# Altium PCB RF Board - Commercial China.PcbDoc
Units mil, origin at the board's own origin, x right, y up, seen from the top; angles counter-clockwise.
Board outline 2000 x 1000 mil, 2 copper layers (Top Layer, Bottom Layer); 17 components, 17 nets, 58 pads, 9 vias.
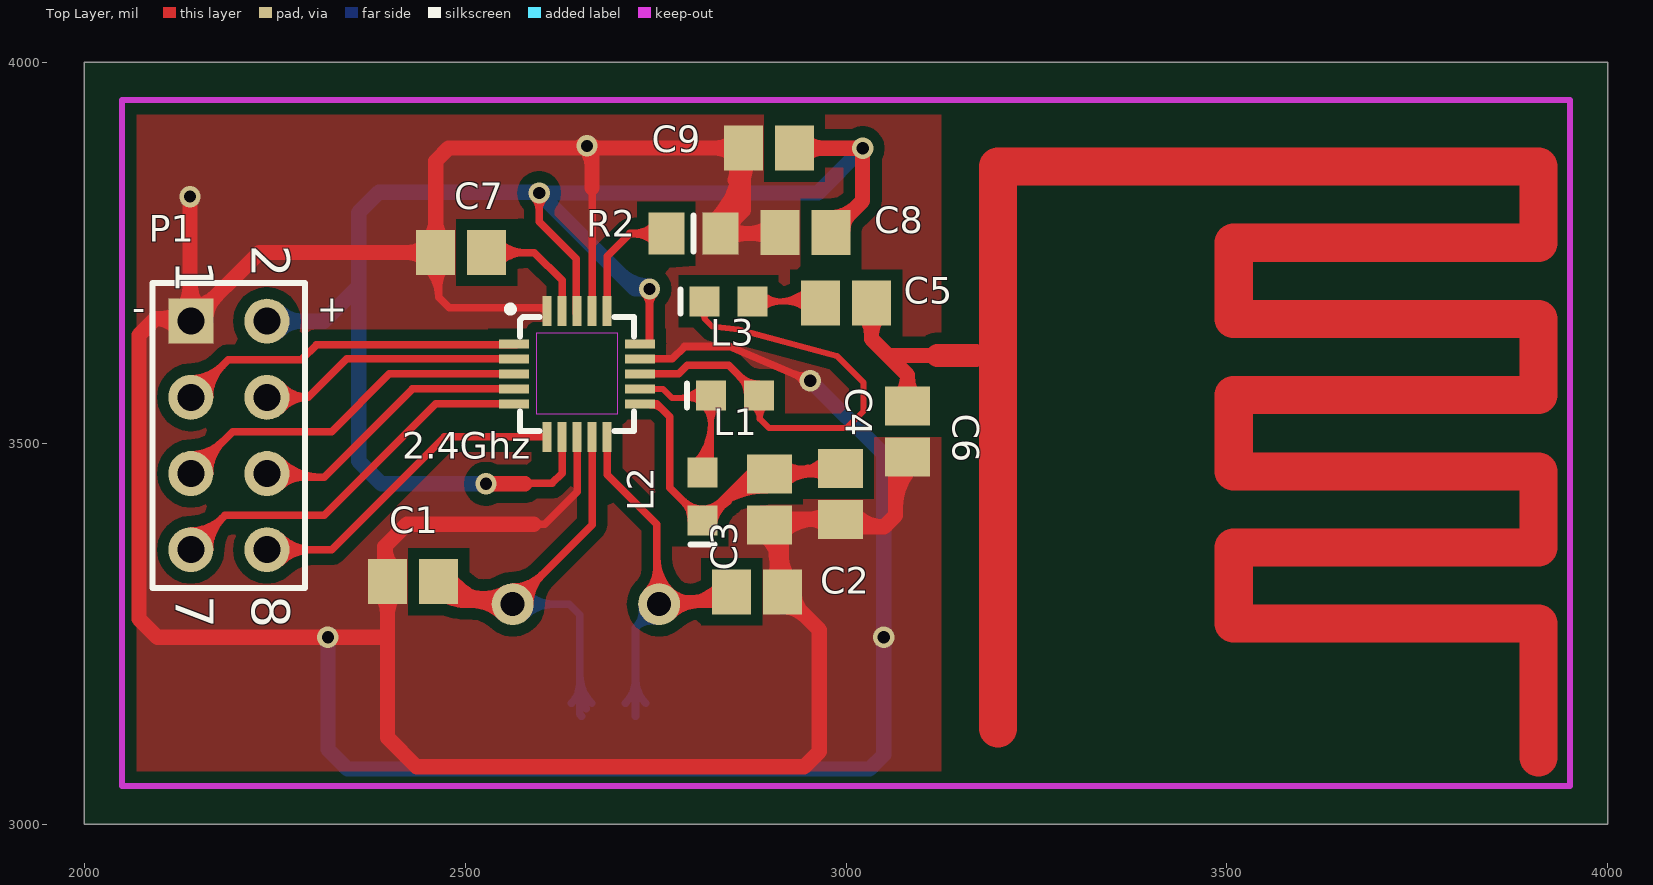
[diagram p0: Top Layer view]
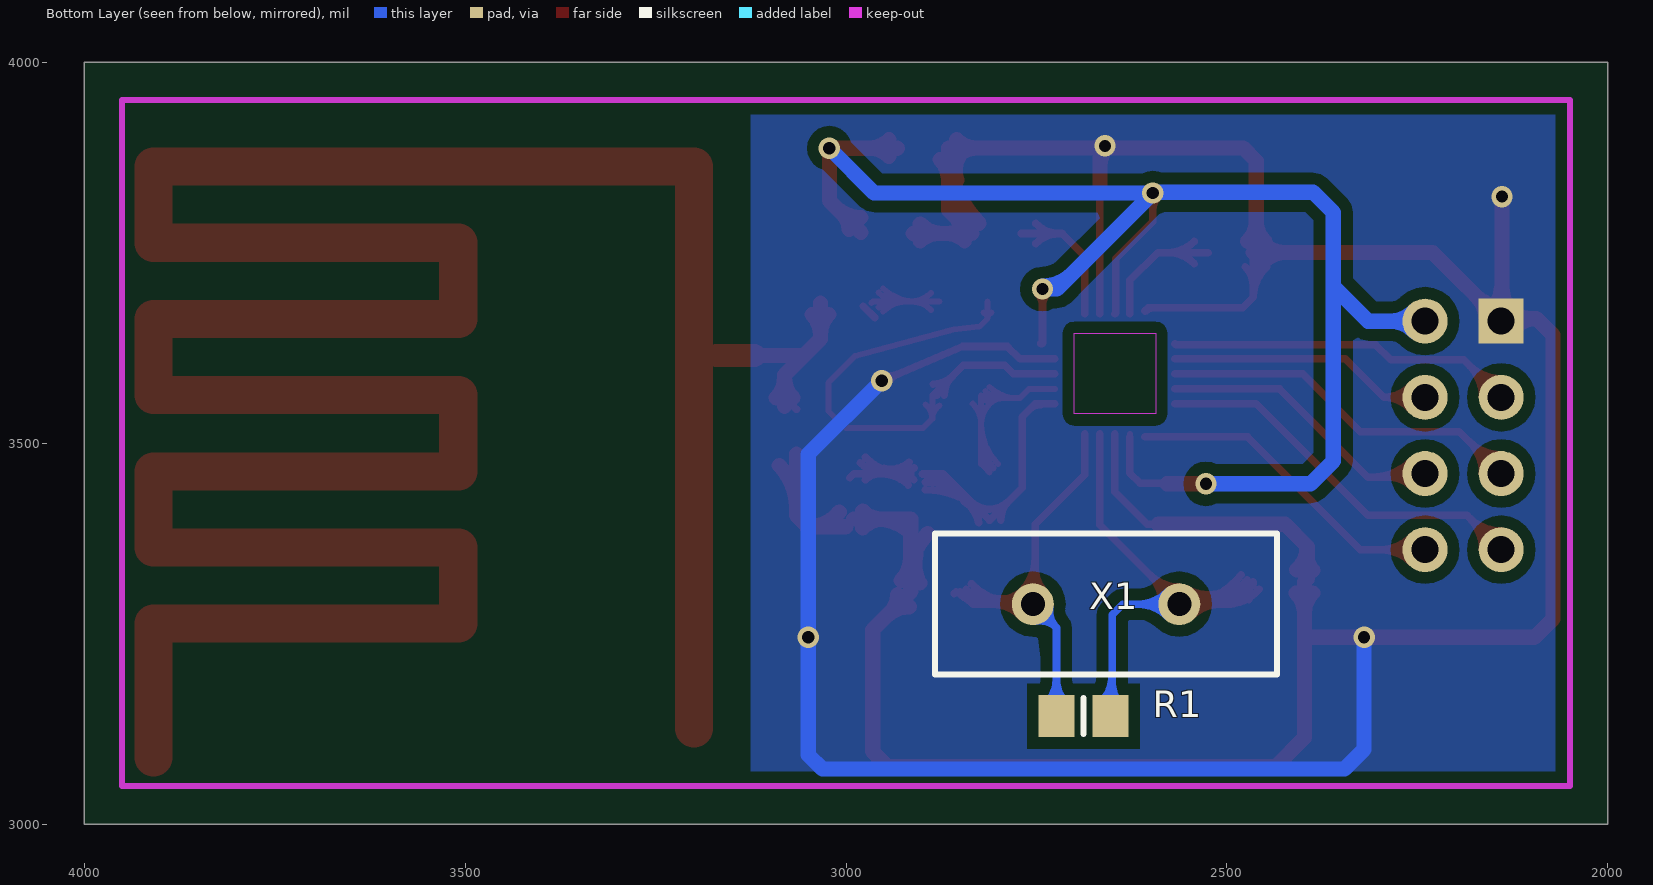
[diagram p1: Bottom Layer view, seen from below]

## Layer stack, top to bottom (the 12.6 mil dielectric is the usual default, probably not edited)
Top Layer: signal copper 1.4
Dielectric: dielectric 12.6, FR-4, Dk 4.8
Bottom Layer: signal copper 1.4

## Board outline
2000,3000 4000,3000 4000,4000 2000,4000

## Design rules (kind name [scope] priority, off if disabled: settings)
Clearance "Polygon Clearance" [InPolygon] p1: gap=15
Clearance [All] p2: gap=8.1
HoleSize [All] p1: absolutevalues=TRUE maxlimit=100 minlimit=16 maxpercent=80.000 minpercent=20.000
MinimumAnnularRing [All] p1: minimumring=6
PolygonConnect [All] p1: connectstyle=Direct reliefconductorwidth=10 reliefentries=4 polygonreliefangle="90 Angle"
RoutingVias [All] p1: holewidth=16 width=28 viastyle="Through Hole" minholewidth=16 minwidth=27 maxholewidth=16 maxwidth=35
SilkscreenOverComponentPads [All] p1: minsilkscreentomaskgap=10
SolderMaskExpansion [All] p1: expansion=4
Width [All] p1: maxlimit=50 minlimit=8 preferedwidth=8
26 further rules are at their usual default settings.

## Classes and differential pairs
component class "2.4Ghz Chip Board": P1
net class SPI[3..0]: SPI0 SPI1 SPI2 SPI3

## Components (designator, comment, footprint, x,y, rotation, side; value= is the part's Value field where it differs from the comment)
2.4Ghz "nRF24L01+" nRF24L01+ 2576.16,3630.12 r0 top (schematic designator "2.4Ghz Chip")
C1 "Cap Semi" CAPC2012N 2431.81,3318.02 r0 top
C2 "Cap Semi" CAPC2012N 2883.35,3304.68 r180 top
C3 "Cap Semi" CAPC2012N 2899.64,3425.9 r90 top
C4 "Cap Semi" CAPC2012N 2992.87,3433.15 r90 top
C5 "Cap Semi" CAPC2012N 3000.12,3683.85 r180 top
C6 "Cap Semi" CAPC2012N 3080.62,3514.92 r90 top
C7 "Cap Semi" CAPC2012N 2495,3750 r0 top
C8 "Cap Semi" CAPC2012N 2946.88,3776.47 r0 top
C9 "Cap Semi" CAPC2012N 2899.02,3887.01 r0 top
L1 "Inductor" INDC1608N 2854.06,3562.65 r0 top
L2 "Inductor" INDC1608N 2811.58,3430.04 r90 top
L3 "Inductor" INDC1608N 2845.77,3685.93 r0 top
P1 "Header 4X2" HDR2X4 2140,3660 r270 top
R1 "Res2" RESC2012N 2688.35,3141.5 r0 bottom
R2 "Res3" RESC2012N 2799.53,3775 r0 top
X1 "16Mhz" "HC-49U - Through Hole" 2658.63,3288.52 r0 bottom

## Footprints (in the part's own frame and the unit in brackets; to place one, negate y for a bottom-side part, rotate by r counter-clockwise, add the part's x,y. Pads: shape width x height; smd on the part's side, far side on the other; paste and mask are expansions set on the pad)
CAPC2012N [mm] "Chip Capacitor, Body 2.0x1.3mm, IPC Medium Density"
  rect 1.3x1.5 smd: 1(-0.85,0) 2(0.85,0)
  body extent -1.1,-0.72 1.1,0.72, height 1.1
"HC-49U - Through Hole" [mm] "Quartz Crystal, Thru-Hole; 2 Leads; Body 11.35 x 4.65 x 13.46 mm (LxWxH max)"
  round 1.4 hole 0.8: 1(-2.44,0) 2(2.44,0)
  silkscreen extent -5.7,-2.35 5.7,2.35
HDR2X4 [mm] "Connector; Header; 4x2 Position"
  rect 1.5x1.5 hole 0.9: 1(0,0)
  round 1.5 hole 0.9: 2(0,2.54) 3(2.54,0) 4(2.54,2.54) 5(5.08,0) 6(5.08,2.54) 7(7.62,0) 8(7.62,2.54)
  silkscreen extent -1.27,-1.27 8.89,3.81
INDC1608N [mm] "Chip Inductor, Body 1.6x0.8mm, IPC Medium Density"
  rect 1x1 smd: 1(-0.8,0) 2(0.8,0)
  silkscreen extent -1.6,-0.4 -1.6,0.4, body extent -0.87,-0.48 0.87,0.48, height 0.71
nRF24L01+ [mm]
  rect 1x0.29 smd: 1(-0.3,0) 2(-0.3,-0.5) 3(-0.3,-1) 4(-0.3,-1.5) 5(-0.3,-2) 11(3.9,-2) 12(3.9,-1.5) 13(3.9,-1) 14(3.9,-0.5) 15(3.9,0)
  rect 0.29x1 smd: 6(0.8,-3.1) 7(1.3,-3.1) 8(1.8,-3.1) 9(2.3,-3.1) 10(2.8,-3.1) 16(2.8,1.1) 17(2.3,1.1) 18(1.8,1.1) 19(1.3,1.1) 20(0.8,1.1)
  Keep-Out Layer region: 0.447,-2.334 3.152,-2.334 3.152,0.357 0.447,0.357
  silkscreen extent -0.49,-2.9 3.7,1.22
RESC2012N [mm] "Chip Resistor, Body 2.0x1.3mm, IPC Medium Density"
  rect 1.2x1.4 smd: 1(-0.9,0) 2(0.9,0)
  silkscreen extent 0,-0.6 0,0.6, body extent -1.07,-0.7 1.07,0.7, height 0.65

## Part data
C1 C2 C3 C4 C5 C6 C7 C8 C9: "Capacitor (Semiconductor SIM Model)"
P1: "Header, 4-Pin, Dual row"
R1 R2: "Resistor"
X1: library part XTAL, "Crystal Oscillator"

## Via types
v1: diameter 28, hole 16, Top Layer to Bottom Layer, 9 vias

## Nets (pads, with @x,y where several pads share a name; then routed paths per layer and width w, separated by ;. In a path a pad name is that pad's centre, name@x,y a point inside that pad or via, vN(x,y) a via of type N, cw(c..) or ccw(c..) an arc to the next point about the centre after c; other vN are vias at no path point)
3.3VCC: 2.4Ghz.7 2.4Ghz.15 2.4Ghz.18 C8.2 C9.2 P1.2 | length 2481.3
  Top Layer w8: 2.4Ghz.7 2.4Ghz.7@2627.34,3512.01
  Top Layer w10: 2579.2,3446.99 2614.06,3446.99 2627.34,3460.27 2.4Ghz.7 ; v1@2590.93,3821.77 cw(c2575.56,3806.4) 2597.29,3806.4 cw(c2619.02,3806.4) v1@2603.65,3821.77 ; v1(2597.29,3828.13) 2597.29,3790.56 2646.15,3741.7 2646.15,3670.37 2.4Ghz.18@2647.03,3669.49 ; v1@2735.72,3695.78 cw(c2720.35,3680.41) 2742.08,3680.41 cw(c2763.81,3680.41) v1@2748.44,3695.78 ; 2.4Ghz.15@2742.08,3635.69 ccw(c2749.25,3635.69) 2.4Ghz.15@2744.18,3630.62 ; v1(2742.08,3702.14) 2742.08,3631.08 2.4Ghz.15@2743.04,3630.12 ; v1@3021.77,3887.01 v1(3021.88,3886.9)
  Top Layer w20: v1(2527.51,3446.52) 2578.73,3446.52 ; C9.2 3021.77,3887.01 3021.77,3817.9 C8.2 ; C9.2@2943.51,3875.99 cw(c2970.12,3849.37) 2970.12,3887.01 cw(c2970.12,3924.65) C9.2@2943.51,3898.03 ; C8.2@2980.34,3796 ccw(c2980.34,3843.14) 3013.68,3809.81 ; C8.2@2995.94,3780.41 cw(c3024.07,3780.41) C8.2@3004.18,3800.3
  Bottom Layer w20: P1.2@2245,3665 P1.2 2314.81,3660 2360.4,3705.59 ; P1.2@2253.81,3646.19 cw(c2287.14,3612.86) 2287.14,3660 cw(c2287.14,3707.14) P1.2@2253.81,3673.81 ; v1(2527.51,3446.52) 2390.27,3446.52 2360.4,3476.39 2360.4,3705.59 ; 2703.16,3722.26 ccw(c2742.08,3761.18) v1@2742.08,3706.14 ; v1(2742.08,3702.14) 2723.28,3702.14 v1(2597.29,3828.13) ; v1(3021.88,3886.9) 2963.11,3828.13 v1(2597.29,3828.13) ; 2360.4,3705.59 2360.4,3802.76 2386.94,3829.3 2596.12,3829.3 v1(2597.29,3828.13)
CE: 2.4Ghz.1 P1.3 | length 605.4
  Top Layer w10: P1.3 2189.34,3609.34 2285.16,3609.34 2305.06,3629.24 2567.41,3629.24 2.4Ghz.1@2568.29,3630.12 ; P1.3@2140,3574.53 ccw(c2140,3609.6) 2164.8,3584.8 ccw(c2189.6,3560) P1.3@2154.53,3560 ; P1.3@2140,3584.53 ccw(c2140,3643.74) 2181.87,3601.87 ccw(c2223.74,3560) P1.3@2164.53,3560
GND: 2.4Ghz.8 2.4Ghz.14 2.4Ghz.17 2.4Ghz.20 C1.1 C2.1 C3.1 C4.1 C6.1 C7.1 C8.1 C9.1 P1.1 R2.2 | length 7561.2
  Top Layer w10: C7.1@2447.86,3730.67 cw(c2413.02,3691.46) 2465.47,3691.46 ; C7.1@2454.5,3738.15 cw(c2432.8,3713.72) 2465.47,3713.72 ; 2465.47,3705.86 cw(c2501.74,3705.86) C7.1@2476.1,3731.5 ; C7.1@2465.47,3750 2465.47,3691.6 2479.38,3677.69 2603.39,3677.69 2.4Ghz.20 ; 2590.13,3393.53 2604.63,3393.53 2647.03,3435.93 2.4Ghz.8 2.4Ghz.8@2647.03,3512.01 ; 2595.65,3677.69 cw(c2595.65,3661.42) 2.4Ghz.20@2607.16,3672.93 ; 2.4Ghz.17@2666.71,3669.49 2.4Ghz.17 2666.71,3835 ; 2.4Ghz.14@2725.77,3610.43 2.4Ghz.14 2771.89,3610.43 2788.11,3626.66 2847.13,3626.66 2847.19,3626.59 v1(2953.17,3581.7) ; C8.1@2911.95,3775 C8.1 ; C2.1@2914.53,3305 C2.1@2915,3305.47 ; v1@2944.83,3578.32 ccw(c2924.69,3570.17) 2933.16,3590.18 ccw(c2941.64,3610.18) v1@2949.79,3590.04 ; C4.1@2990,3400.47 C4.1@3000.47,3390
  Top Layer w20: 2100.85,3663.31 ccw(c2100.85,3699.15) 2126.19,3673.81 ccw(c2095.27,3704.73) 2139,3704.73 ; P1.1@2124.5,3648.12 ccw(c2093.71,3624.51) 2093.71,3663.31 ; 2139,3709.56 ccw(c2189.56,3709.56) P1.1@2153.81,3673.81 ; v1(2139,3823.46) P1.1@2139,3661 ; P1.1@2140,3679.53 ccw(c2140,3726.67) 2173.34,3693.34 ccw(c2206.67,3660) P1.1@2159.53,3660 ; C1.1@2387.32,3303.06 cw(c2360.71,3276.44) 2398.35,3276.44 cw(c2435.98,3276.44) C1.1@2409.37,3303.06 ; C1.1@2387.32,3332.98 ccw(c2369.75,3350.55) 2394.6,3350.55 ; C1.1@2408.57,3333.73 cw(c2435.19,3364.37) 2394.6,3364.37 ; 2423.75,3393.52 2394.6,3364.37 ; 2423.75,3393.53 2590.13,3393.53 ; C7.1@2450.51,3738.98 ccw(c2423.9,3712.36) 2423.9,3750 ccw(c2423.9,3787.64) C7.1@2450.51,3761.02 ; C7.1@2450.51,3764.96 ccw(c2423.9,3791.58) 2461.54,3791.58 ccw(c2499.17,3791.58) C7.1@2472.56,3764.96 ; C7.1@2465.47,3750 C7.1 ; 2643.41,3887.13 ccw(c2643.41,3906.59) v1@2657.17,3892.83 ; v1@2657.17,3887.17 cw(c2634.14,3864.14) 2666.71,3864.14 ; v1@2662.83,3892.83 ccw(c2676.59,3906.59) 2676.59,3887.13 ; 2666.71,3835 2666.71,3883.29 v1@2662.87,3887.13 ; R2.2@2825.33,3788.57 ccw(c2728.21,3885.69) C9.1@2865.56,3885.69 ; 2827.63,3887.13 cw(c2827.63,3849.08) C9.1@2854.53,3875.99 ; 2828.21,3887.13 ccw(c2828.21,3924.36) C9.1@2854.53,3898.03 ; R2.2@2834.96,3792.56 ccw(c2834.96,3834.95) 2864.94,3804.98 ; R2.2@2839.47,3774.43 ccw(c2776.5,3837.4) 2865.56,3837.4 ; R2.2@2844.59,3765.37 cw(c2867.85,3742.11) 2867.85,3775 cw(c2867.85,3807.89) R2.2@2844.59,3784.63 ; R2.2@2848.58,3778.94 cw(c2871.96,3778.94) R2.2@2855.43,3795.47 ; C9.1@2852.05,3875.28 cw(c2821.46,3857.61) 2855.58,3848.47 ; C9.1@2854.53,3872.05 cw(c2827.92,3845.43) 2865.56,3845.43 cw(c2903.19,3845.43) C9.1@2876.58,3872.05 ; 2854.74,3845.31 cw(c2893.32,3834.98) C9.1@2873.35,3869.57 ; 2872.23,3775 ccw(c2872.23,3817.66) C8.1@2902.39,3787.49 ; 2879.33,3775 cw(c2879.33,3742.38) C8.1@2902.39,3765.45 ; C3.1@2892.55,3381.41 cw(c2838.36,3327.22) C2.1@2915,3327.22 ; C2.1@2903.31,3316.41 ccw(c2861.66,3340.46) 2908.12,3352.91 ; C2.1@2905.79,3319.64 ccw(c2883.56,3341.88) 2915,3341.88 ; 2911.94,3338.63 ccw(c2938.2,3345.66) C2.1@2924.61,3322.12 ; C8.1@2911.95,3775 R2.2 2865.56,3805.59 C9.1 2865.44,3887.13 v1@2662.87,3887.13 ; C2.1@2914.53,3305 2965,3254.53 2965,3095 2945,3075 2436.63,3075 2398.35,3113.28 2398.35,3244.28 ; C3.1@2914.6,3381.41 cw(c2960.62,3335.39) 2960.62,3400.47 ; C2.1@2915,3305.47 2915,3400.47 C4.1@2990,3400.47 ; 2915,3350.64 ccw(c2958.83,3350.64) C2.1@2927.84,3319.64 ; C2.1@2916.81,3285.15 cw(c2916.81,3242.76) 2946.79,3272.74 ; C2.1@2932.41,3300.74 ccw(c2965.29,3300.74) C2.1@2942.04,3277.49 ; 2949.39,3400.47 cw(c2949.39,3360.15) C4.1@2977.91,3388.66 ; 2953.19,3400.47 ccw(c2953.19,3435.42) C4.1@2977.91,3410.71 ; C4.1@3000.47,3390 3050,3390 ; C4.1@3008.89,3409.53 ccw(c3050,3443.01) 3050,3390 ; 3065,3415.61 cw(c3142.53,3415.61) C6.1@3087.71,3470.43 ; C6.1@3065,3485.47 3065,3405 3050,3390 ; 2093.71,3663.31 2136.69,3663.31 P1.1@2139,3661 ; 2093.71,3663.31 2072.1,3641.7 2072.1,3269.2 2096.3,3245 v1(2320,3245) 2397.63,3245 2398.35,3244.28 ; P1.1@2139,3661 2131.71,3653.71 P1.1 ; P1.1@2139,3661 P1.1 ; P1.1 2230,3750 C7.1 ; 2394.6,3364.37 2394.6,3321.77 C1.1 2398.35,3244.28 ; C7.1 2461.54,3870.29 2478.38,3887.13 v1@2660,3887.13 ; v1@2660,3887.13 v1(2660,3890) v1@2662.87,3887.13 ; v1@2660,3887.13 v1@2662.87,3887.13
  Bottom Layer w20: v1(2320,3245) 2320,3097.79 2345.69,3072.1 3030.85,3072.1 3049.61,3090.86 v1(3049.61,3245.14) 3049.61,3485.26 v1(2953.17,3581.7)
IRQ: 2.4Ghz.6 P1.8 | length 577.1
  Top Layer w10: P1.8 2325,3360 2473.07,3508.07 2.4Ghz.6 ; P1.8@2250.27,3349.73 cw(c2275.07,3324.93) 2275.07,3360 cw(c2275.07,3395.07) P1.8@2250.27,3370.27 ; P1.8@2257.34,3342.66 cw(c2299.21,3300.79) 2299.21,3360 cw(c2299.21,3419.21) P1.8@2257.34,3377.34
"Net2.4Ghz Chip_9": 2.4Ghz.9 C1.2 R1.1 X1.1 | length 1649.9
  Top Layer w10: C1.2@2457.99,3308.13 ccw(c2499.32,3341.89) 2499.32,3288.52 ; C1.2 2494.77,3288.52 ; C1.2@2465.73,3314.46 ccw(c2520.4,3359.11) 2520.4,3288.52 ; C1.2@2471.28,3294.39 cw(c2478.14,3271.89) 2494.77,3288.52 ; C1.2@2473.48,3320.78 ccw(c2541.48,3376.33) X1.1@2541.48,3288.52 ; C1.2@2481.22,3327.11 ccw(c2562.56,3393.54) X1.1 ; C1.2@2485.81,3312.59 ccw(c2516.61,3310.35) 2494.77,3288.52 ; 2515.43,3294.05 ccw(c2522.15,3325.7) X1.1@2545.97,3303.79 ; 2518.73,3293.35 cw(c2510.52,3254.71) X1.1@2543.65,3276.23 ; 2532.59,3290.41 ccw(c2537.16,3311.9) X1.1@2553.32,3297.02 ; X1.1@2543.02,3277.26 ccw(c2496.02,3250.2) 2510.05,3302.59 ccw(c2524.09,3354.97) X1.1@2551.26,3308.04 ; X1.1@2546.62,3272.57 ccw(c2508.1,3234.06) 2508.1,3288.52 ccw(c2508.1,3342.98) X1.1@2546.62,3304.47 ; X1.1@2551.68,3282.25 ccw(c2525.52,3267.19) 2533.33,3296.35 ccw(c2541.14,3325.51) X1.1@2556.27,3299.39 ; X1.1@2553.69,3279.64 ccw(c2532.25,3258.2) 2532.25,3288.52 ccw(c2532.25,3318.84) X1.1@2553.69,3297.4 ; X1.1@2562.57,3301.08 ccw(c2562.57,3331.4) 2584.01,3309.96 ccw(c2605.45,3288.52) X1.1@2575.13,3288.52 ; X1.1@2562.57,3311.08 ccw(c2562.57,3365.54) 2601.08,3327.03 ccw(c2639.59,3288.52) X1.1@2585.13,3288.52 ; 2.4Ghz.9@2666.71,3512.01 2.4Ghz.9 2666.71,3392.66 X1.1 ; 2494.77,3288.52 X1.1
  Bottom Layer w10: X1.1 2636.8,3288.52 2650.45,3274.87 2650.45,3143.97 R1.1 ; X1.1@2571.45,3279.64 cw(c2592.89,3258.2) 2592.89,3288.52 cw(c2592.89,3318.84) X1.1@2571.45,3297.4 ; X1.1@2578.52,3272.57 cw(c2617.03,3234.06) 2617.03,3288.52 cw(c2617.03,3342.98) X1.1@2578.52,3304.47 ; R1.1@2639.75,3158.6 ccw(c2613.92,3184.44) 2650.45,3184.44 ; 2650.45,3172.21 ccw(c2679.69,3172.21) R1.1@2659.01,3151.53 ; 2650.45,3196.35 ccw(c2703.83,3196.35) R1.1@2666.08,3158.6
"Net2.4Ghz Chip_10": 2.4Ghz.10 C2.2 R1.2 X1.2 | length 1150.1
  Top Layer w10: 2.4Ghz.10@2686.4,3512.01 2.4Ghz.10 2686.4,3458.6 2751.59,3393.41 2751.59,3291.63 X1.2 2833.73,3288.52 C2.2 ; X1.2@2738.74,3304.47 ccw(c2707.73,3335.48) 2751.59,3335.48 ; 2751.59,3326.34 ccw(c2792.52,3326.34) 2763.57,3297.4 ccw(c2785.01,3318.84) 2785.01,3288.52 ccw(c2785.01,3258.2) X1.2@2763.57,3279.64 ; 2751.59,3350.49 ccw(c2816.66,3350.49) 2770.64,3304.47 ccw(c2809.16,3342.98) 2809.16,3288.52 ccw(c2809.16,3234.06) X1.2@2770.64,3272.57 ; X1.2@2763.15,3297.81 ccw(c2779.86,3316.15) 2785.5,3291.99 ; X1.2@2769.88,3305.2 ccw(c2795.4,3333.21) 2804.02,3296.31 ; X1.2@2770.67,3288.52 ccw(c2770.67,3379.96) C2.2@2835.33,3315.3 ; X1.2@2773.86,3276.62 cw(c2809.58,3254.42) 2800.01,3295.38 ; 2794.81,3288.52 ccw(c2794.81,3355.82) C2.2@2842.4,3308.23 ; 2818.95,3288.52 ccw(c2818.95,3331.68) C2.2@2849.47,3301.16 ; C2.2@2855.47,3305 C2.2@2857.99,3302.48
  Bottom Layer w10: R1.2@2710.62,3158.6 ccw(c2678.83,3190.39) 2723.78,3190.39 ccw(c2768.74,3190.39) R1.2@2736.95,3158.6 ; R1.2 2723.78,3257.61 ; X1.2@2732.45,3284.76 cw(c2701.82,3279.58) 2723.78,3257.61 ; X1.2@2750.93,3266.28 ccw(c2745.75,3235.64) 2723.78,3257.61 ; X1.2 2723.78,3257.61
"Net2.4Ghz Chip_11": 2.4Ghz.11 C3.2 C4.2 L2.1 | length 1076.6
  Top Layer w10: 2.4Ghz.11@2725.77,3551.38 2751.83,3551.38 2768.58,3534.63 2768.58,3441.54 L2.1 2872.4,3459.36 C3.2 ; 2.4Ghz.11@2743.68,3550.67 cw(c2743.68,3529.28) 2758.8,3544.41 ; L2.1@2796.89,3398.54 ccw(c2761.44,3398.54) 2786.51,3423.61 ccw(c2811.58,3448.68) 2811.58,3413.23 ccw(c2811.58,3448.68) 2836.65,3423.61 ccw(c2861.72,3398.54) L2.1@2826.27,3398.54 ; L2.1@2814.63,3412.91 ccw(c2820.07,3438.59) 2834.38,3416.58 ; L2.1@2820.77,3407.74 cw(c2895.7,3332.81) C3.2@2895.7,3438.77 ; L2.1@2825.95,3395.5 cw(c2869.63,3386.24) 2845.29,3423.68 ; 2837.84,3424.81 cw(c2895.7,3366.95) C3.2@2895.7,3448.77 ; 2854.92,3441.88 cw(c2895.7,3401.09) C3.2@2895.7,3458.77 ; C3.2@2910.62,3467.27 ccw(c2926.17,3484.73) 2932.04,3462.1 ; C3.2@2911.07,3451.88 cw(c2929.54,3433.4) 2929.54,3459.53 ; C3.2@2915,3459.53 2990,3459.53 C4.2@2995,3454.53 ; C3.2@2917.27,3474.74 ccw(c2941.16,3501.56) 2950.16,3466.79 ; C3.2@2918.14,3444.8 cw(c2953.68,3409.26) 2953.68,3459.53 ; C3.2@2918.14,3473.92 ccw(c2952.89,3508.68) 2952.89,3459.53 ; C3.2@2921.32,3448.92 cw(c2950.95,3431.48) 2942.33,3464.76 ; C3.2@2922.11,3459.53 ccw(c2922.11,3533.43) C4.2@2974.37,3481.17 ; 2946.26,3459.53 ccw(c2946.26,3509.29) C4.2@2981.44,3474.1 ; 2956.33,3459.53 cw(c2956.33,3434.01) C4.2@2974.37,3452.05
"Net2.4Ghz Chip_12": 2.4Ghz.12 L1.1 L2.2 | length 489.8
  Top Layer w8: 2.4Ghz.12@2725.77,3571.07 2759.6,3571.07 2771.76,3558.9 L1.1@2818.81,3558.9 ; 2775.64,3558.9 ccw(c2775.64,3609.57) L1.1@2811.47,3573.74 ; 2793.75,3558.9 cw(c2793.75,3533.84) 2811.47,3551.56 cw(c2784.7,3524.78) 2822.56,3524.78 cw(c2860.43,3524.78) L1.1@2833.65,3551.56 ; 2794.96,3558.9 ccw(c2794.96,3590.26) L1.1@2817.13,3568.08 ; L2.2@2800.49,3472.63 ccw(c2747.2,3525.92) 2822.56,3525.92 ; L2.2@2806.15,3466.97 ccw(c2766.51,3506.61) 2822.56,3506.61 ; L2.2 2822.56,3472.52 L1.1 L1.1@2818.81,3558.9 ; L2.2@2811.8,3461.31 ccw(c2785.82,3487.29) 2822.56,3487.29 ; L1.1@2815.23,3555.32 L1.1@2818.81,3558.9
"Net2.4Ghz Chip_13": 2.4Ghz.13 L1.2 L3.1 | length 784.4
  Top Layer w8: L3.1@2808.85,3671.21 cw(c2805.97,3663.43) 2814.27,3663.43 ; L3.1 2814.27,3663.43 ; L3.1@2819.7,3671.21 ccw(c2822.57,3663.43) 2814.27,3663.43 ; L1.2@2877.08,3549.45 cw(c2865.81,3531.91) 2886.66,3531.91 cw(c2910.66,3531.91) L1.2@2895.48,3550.5 ; L1.2@2879.05,3562.65 2880.46,3562.65 L1.2 2886.66,3561.55 2886.66,3531.93 2898.77,3519.82 3000.89,3519.82 3023.13,3542.06 3023.13,3579.18 2987.86,3614.45 2858.77,3648.91 2824.77,3652.93 2814.27,3663.43
  Top Layer w10: 2.4Ghz.13@2725.77,3590.75 2780.68,3590.75 2791.88,3601.95 2846.26,3601.95 L1.2 L1.2@2880.46,3562.65 ; L1.2@2870.87,3562.65 ccw(c2835.42,3562.65) 2860.49,3587.72 ccw(c2885.56,3612.79) L1.2@2885.56,3577.34
"Net2.4Ghz Chip_16": 2.4Ghz.16 R2.1 | length 242.2
  Top Layer w10: 2.4Ghz.16@2686.4,3669.49 2686.4,3745.06 2716.34,3775 R2.1@2770,3775 ; R2.1@2750.93,3761.83 ccw(c2719.14,3730.04) 2719.14,3775 ccw(c2719.14,3819.96) R2.1@2750.93,3788.17
"Net2.4Ghz Chip_19": 2.4Ghz.19 C7.2 | length 240.1
  Top Layer w10: C7.2@2524.53,3750 2590.98,3750 2627.34,3713.64 2.4Ghz.19 2.4Ghz.19@2627.34,3669.49 ; C7.2@2543.02,3735.44 cw(c2578.17,3700.29) 2578.17,3750 cw(c2578.17,3799.71) C7.2@2543.02,3764.56
NetC5_1: C5.1 C6.2 | length 5018.3
  Top Layer w10: C6.2@3065,3544.53 C6.2@3070,3549.53
  Top Layer w20: C5.1@3022.56,3668.89 cw(c2995.95,3642.27) 3033.58,3642.27 cw(c3071.22,3642.27) C5.1@3044.61,3668.89 ; C5.1 3033.58,3636.42 3055,3615 ; C6.2@3069.6,3559.41 ccw(c3042.98,3586.02) 3080.62,3586.02 ccw(c3118.26,3586.02) C6.2@3091.64,3559.41 ; C6.2 3080.62,3589.38 3055,3615 ; 3120,3615 3055,3615
  Top Layer w30: 3120,3615 3170,3615
  Top Layer w50: 3199.28,3125.3 3199.28,3862.9 3908.95,3862.9 3908.95,3762.9 3508.95,3762.9 3508.95,3662.9 3908.95,3662.9 3908.95,3562.9 3508.95,3562.9 3508.95,3462.9 3908.95,3462.9 3908.95,3362.9 3508.95,3362.9 3508.95,3262.9 3908.95,3262.9 3908.95,3087.1
NetC5_2: C5.2 L3.2 | length 304.1
  Top Layer w8: L3.2 2964.58,3685.93 C5.2 ; L3.2@2888.36,3674.84 cw(c2915.13,3648.06) 2915.13,3685.93 cw(c2915.13,3723.8) L3.2@2888.36,3697.02 ; 2910.05,3685.93 ccw(c2910.05,3744.39) C5.2@2951.39,3703.05 ; 2919.01,3685.93 cw(c2919.01,3640.15) C5.2@2951.39,3672.52 ; 2929.36,3685.93 ccw(c2929.36,3725.08) C5.2@2957.05,3697.4 ; 2938.33,3685.93 cw(c2938.33,3659.46) C5.2@2957.05,3678.18
  Top Layer w10: C5.2@2962.42,3664.8 C5.2@2977.23,3679.61
SPI0: 2.4Ghz.2 P1.4 | length 478.6
  Top Layer w10: P1.4 2294.34,3560 ; P1.4@2250.9,3550.39 cw(c2272.18,3531.62) 2272.18,3560 cw(c2272.18,3588.38) P1.4@2250.9,3569.61 ; P1.4@2258.4,3543.78 cw(c2294.33,3512.09) 2294.33,3560 ; P1.4@2258.4,3576.22 ccw(c2294.33,3607.91) 2294.33,3560 ; 2.4Ghz.2@2568.29,3610.43 2344.77,3610.43 2294.34,3560
SPI1: 2.4Ghz.3 P1.5 | length 630.6
  Top Layer w10: P1.5 2195,3515 2325,3515 2400.75,3590.75 2.4Ghz.3@2568.29,3590.75 ; P1.5@2140,3474.53 ccw(c2140,3509.6) 2164.8,3484.8 ccw(c2189.6,3460) P1.5@2154.53,3460 ; P1.5@2140,3484.53 ccw(c2140,3543.74) 2181.87,3501.87 ccw(c2223.74,3460) P1.5@2164.53,3460
SPI2: 2.4Ghz.4 P1.6 | length 512.4
  Top Layer w10: P1.6 2245,3455 2315,3455 2431.07,3571.07 2.4Ghz.4@2568.29,3571.07 ; P1.6@2250.27,3470.27 ccw(c2287.14,3507.14) 2287.14,3455 ccw(c2287.14,3412.86) P1.6@2257.34,3442.66 ; P1.6@2257.34,3477.34 ccw(c2311.29,3531.29) 2311.29,3455
SPI3: 2.4Ghz.5 P1.7 | length 655.7
  Top Layer w10: P1.7 2185,3405 2315,3405 2461.38,3551.38 2.4Ghz.5@2568.29,3551.38 ; P1.7@2140,3374.53 ccw(c2140,3409.6) 2164.8,3384.8 ccw(c2189.6,3360) P1.7@2154.53,3360 ; P1.7@2140,3384.53 ccw(c2140,3443.74) 2181.87,3401.87 ccw(c2223.74,3360) P1.7@2164.53,3360

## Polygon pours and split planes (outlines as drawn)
GND on Top Layer "Top Layer-GND" (solid, pour order 4): 2025,3975 3125,3975 3125,3025 2025,3025
GND on Bottom Layer "Bottom Layer-No Net" (solid, pour order 2): 2025,3980 2030,3975 3125,3975 3125,3025 2025,3025

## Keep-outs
Keep-Out Layer:
  lines w8: 2050,3050 3950,3050 3950,3950 2050,3950 2050,3050

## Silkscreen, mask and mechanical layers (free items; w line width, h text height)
Top Overlay:
  text "-" at 2062.89,3649.58 h60
  text "+" at 2305.63,3647.36 h60
Drill Drawing:
  text ".LEGEND" at 4200,3200 h60
  text "Drill Drawing." at 4200,3100 h60

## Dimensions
2050,3050 to 3950,3050 on Mechanical 1
2050,3050 to 2050,3950 on Mechanical 1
